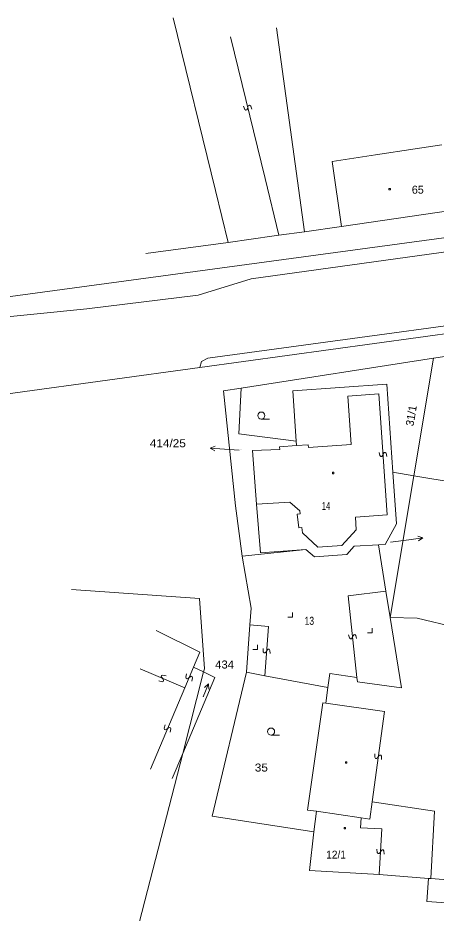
# Model space of a CAD drawing. Extents: x -736847 to -736508, y -1028413 to -1028271.
# Drawn here: x -736724.5 to -736680.1, y -1028365.6 to -1028270.6 of the extents above; entities that cross this region are included whole.
import ezdxf
from ezdxf.enums import TextEntityAlignment as Align

# ---------------------------------------------------------------- set-up
doc = ezdxf.new("R2010")
doc.units = 0
doc.header["$LTSCALE"] = 0.2
doc.layers.add('1', color=7, linetype='Continuous', lineweight=13)
doc.layers.add('2', color=7, linetype='Continuous', lineweight=13)

msp = doc.modelspace()

# ---------------------------------------------------------------- linework, layer by layer
at = {"layer": '1'}
for p, q in [((-736708.02, -1028270.56), (-736703.53, -1028288.89)), ((-736697.06, -1028271.61), (-736694.09, -1028293.26)), ((-736701.96, -1028272.58), (-736698.28, -1028287.61)), ((-736682.37, -1028284.46), (-736686.58, -1028285.1)), ((-736679.54, -1028284.04), (-736682.37, -1028284.46)), ((-736686.58, -1028285.1), (-736691.15, -1028285.79)), ((-736690.18, -1028292.72), (-736691.15, -1028285.79)), ((-736698.28, -1028287.61), (-736696.81, -1028293.63)), ((-736748.87, -1028303.31), (-736632.81, -1028287.63)), ((-736702.18, -1028294.39), (-736703.53, -1028288.89)), ((-736696.81, -1028293.63), (-736694.09, -1028293.26)), ((-736696.81, -1028293.63), (-736697.3, -1028293.7)), ((-736676.66, -1028306.12), (-736680.4, -1028306.7)), ((-736700.82, -1028309.86), (-736680.4, -1028306.7)), ((-736680.4, -1028306.7), (-736682.5, -1028319.17)), ((-736685.37, -1028309.44), (-736695.35, -1028310.15)), ((-736684.72, -1028318.78), (-736685.37, -1028309.44)), ((-736702.69, -1028310.15), (-736700.82, -1028309.86)), ((-736700.82, -1028309.86), (-736701.05, -1028314.73)), ((-736695.35, -1028310.15), (-736694.97, -1028315.51)), ((-736689.49, -1028310.7), (-736686.2, -1028310.48)), ((-736689.49, -1028310.7), (-736689.15, -1028315.84)), ((-736686.2, -1028310.48), (-736685.34, -1028323.33)), ((-736701.05, -1028314.73), (-736694.97, -1028315.51)), ((-736694.94, -1028315.97), (-736696.74, -1028316.09)), ((-736696.73, -1028316.37), (-736696.74, -1028316.09)), ((-736694.97, -1028315.51), (-736694.94, -1028315.97)), ((-736694.94, -1028315.97), (-736693.7, -1028315.87)), ((-736693.7, -1028315.87), (-736693.68, -1028316.17)), ((-736693.68, -1028316.17), (-736689.15, -1028315.84)), ((-736701.03, -1028316.44), (-736702.6, -1028316.34)), ((-736699.6, -1028316.49), (-736696.73, -1028316.37)), ((-736699.18, -1028322.18), (-736699.6, -1028316.49)), ((-736684.72, -1028318.78), (-736684.33, -1028324.26)), ((-736684.72, -1028318.78), (-736682.5, -1028319.17)), ((-736695.66, -1028321.96), (-736699.18, -1028322.18)), ((-736698.75, -1028327.35), (-736699.18, -1028322.18)), ((-736694.6, -1028322.9), (-736695.66, -1028321.96)), ((-736694.55, -1028323.21), (-736694.86, -1028323.26)), ((-736694.86, -1028323.26), (-736694.7, -1028324.7)), ((-736694.6, -1028322.9), (-736694.55, -1028323.21)), ((-736685.34, -1028323.33), (-736688.7, -1028323.55)), ((-736688.7, -1028323.55), (-736688.62, -1028324.9)), ((-736694.7, -1028324.7), (-736694.38, -1028324.66)), ((-736694.38, -1028324.66), (-736694.32, -1028325.23)), ((-736685.53, -1028326.45), (-736684.33, -1028324.26)), ((-736692.7, -1028326.74), (-736694.32, -1028325.23)), ((-736688.62, -1028324.9), (-736690.12, -1028326.57)), ((-736690.12, -1028326.57), (-736692.7, -1028326.74)), ((-736686.26, -1028326.5), (-736688.82, -1028326.65)), ((-736686.26, -1028326.5), (-736685.53, -1028326.45)), ((-736684.99, -1028326.23), (-736683.04, -1028325.97)), ((-736700.72, -1028327.72), (-736693.94, -1028326.99)), ((-736693.94, -1028326.99), (-736698.75, -1028327.35)), ((-736693.02, -1028327.76), (-736693.94, -1028326.99)), ((-736689.62, -1028327.51), (-736693.02, -1028327.76)), ((-736688.82, -1028326.65), (-736689.62, -1028327.51)), ((-736699.76, -1028333.24), (-736700.72, -1028327.72)), ((-736699.89, -1028335.01), (-736697.92, -1028335.16)), ((-736685.01, -1028334.2), (-736682.13, -1028334.28)), ((-736685.01, -1028334.2), (-736683.82, -1028341.69)), ((-736661.35, -1028339.36), (-736682.13, -1028334.28)), ((-736709.82, -1028335.6), (-736705.19, -1028337.88)), ((-736698.31, -1028340.39), (-736697.92, -1028335.16)), ((-736705.86, -1028339.48), (-736705.19, -1028337.88)), ((-736706.8, -1028341.69), (-736711.54, -1028339.68)), ((-736705.86, -1028339.48), (-736704.8, -1028340)), ((-736704.72, -1028339.68), (-736704.8, -1028340)), ((-736704.8, -1028340), (-736707.02, -1028348.65)), ((-736703.61, -1028340.59), (-736707.02, -1028348.65)), ((-736704.8, -1028340), (-736703.61, -1028340.59)), ((-736703.9, -1028355.29), (-736700.26, -1028340.03)), ((-736683.82, -1028341.69), (-736688.48, -1028341.04)), ((-736707.02, -1028348.65), (-736711.92, -1028367.73)), ((-736707.02, -1028348.65), (-736708.14, -1028351.3)), ((-736692.83, -1028354.78), (-736693.77, -1028354.66)), ((-736680.68, -1028361.93), (-736680.3, -1028354.79)), ((-736693.09, -1028356.97), (-736703.9, -1028355.29)), ((-736688.07, -1028355.5), (-736687.18, -1028355.63)), ((-736693.57, -1028361.09), (-736686.16, -1028361.49)), ((-736686.16, -1028361.49), (-736680.95, -1028361.91)), ((-736671.76, -1028362.66), (-736680.68, -1028361.93))]:
    msp.add_line(p, q, dxfattribs=at)
for points in [[(-736847.11, -1028304.1), (-736847.14, -1028305.98), (-736789.15, -1028305.56), (-736765.17, -1028304.89), (-736752.25, -1028304.39), (-736741.06, -1028303.76), (-736733.02, -1028303.04), (-736717.19, -1028301.44), (-736705.39, -1028300.01), (-736699.76, -1028298.26), (-736645.39, -1028290.74), (-736606.84, -1028284.63), (-736586.11, -1028282.62), (-736567.68, -1028281.15), (-736549.73, -1028280.36), (-736529.75, -1028279.79), (-736523.28, -1028279.48), (-736516.84, -1028278.77), (-736513.8, -1028278.17), (-736508.09, -1028276.55)], [(-736694.09, -1028293.26), (-736690.18, -1028292.72), (-736675.43, -1028290.55), (-736672.4, -1028290.07), (-736659.12, -1028288.32), (-736657.95, -1028288.15), (-736651.64, -1028287.22), (-736648.15, -1028286.77), (-736642.63, -1028286), (-736641.29, -1028285.81)], [(-736697.3, -1028293.7), (-736702.18, -1028294.39), (-736710.94, -1028295.58)], [(-736617.32, -1028295.6), (-736658.87, -1028301.31), (-736705.21, -1028307.67), (-736744.41, -1028313.05)], [(-736705.21, -1028307.67), (-736705.02, -1028307.05), (-736704.37, -1028306.69), (-736661.17, -1028300.8), (-736659.94, -1028300.93), (-736658.87, -1028301.31)], [(-736702.69, -1028310.15), (-736701.41, -1028322.36), (-736700.72, -1028327.72)], [(-736685.01, -1028334.2), (-736682.5, -1028319.17), (-736678.02, -1028319.93), (-736677.09, -1028310.49)], [(-736686.26, -1028326.5), (-736685.46, -1028331.41), (-736685.01, -1028334.2)], [(-736718.81, -1028331.23), (-736705.22, -1028332.2), (-736704.72, -1028339.68)], [(-736688.53, -1028340.59), (-736689.45, -1028331.92), (-736685.46, -1028331.41)], [(-736700.26, -1028340.03), (-736699.89, -1028335.01), (-736699.76, -1028333.24)], [(-736710.45, -1028350.32), (-736706.8, -1028341.69), (-736705.86, -1028339.48)], [(-736660.48, -1028339.57), (-736666.59, -1028365.34), (-736681.13, -1028364.37)], [(-736691.61, -1028341.63), (-736698.31, -1028340.39), (-736700.26, -1028340.03)], [(-736691.85, -1028343.31), (-736691.61, -1028341.63), (-736691.41, -1028340.16)], [(-736691.41, -1028340.16), (-736688.53, -1028340.59), (-736688.48, -1028341.04)], [(-736693.77, -1028354.66), (-736692.15, -1028343.27), (-736691.85, -1028343.31)], [(-736686.93, -1028353.8), (-736685.62, -1028344.21), (-736691.85, -1028343.31)], [(-736680.3, -1028354.79), (-736686.93, -1028353.8), (-736687.18, -1028355.63)], [(-736688.07, -1028355.5), (-736692.83, -1028354.78), (-736693.09, -1028356.97), (-736693.57, -1028361.09)], [(-736688.07, -1028355.5), (-736688.17, -1028356.53), (-736685.9, -1028356.65), (-736686.16, -1028361.49)], [(-736681.13, -1028364.37), (-736680.95, -1028361.91), (-736680.68, -1028361.93)]]:
    msp.add_lwpolyline(points, dxfattribs=at)
at = {"layer": '2'}
for p, q in [((-736698.68, -1028313.15), (-736697.805, -1028313.15)), ((-736704.096, -1028316.241), (-736703.581, -1028316.024)), ((-736681.552, -1028325.773), (-736682.015, -1028326.086)), ((-736695.36, -1028334.17), (-736695.86, -1028334.17)), ((-736695.36, -1028334.17), (-736695.36, -1028333.67)), ((-736686.93, -1028335.86), (-736687.43, -1028335.86)), ((-736686.93, -1028335.86), (-736686.93, -1028335.36)), ((-736699.07, -1028337.61), (-736699.57, -1028337.61)), ((-736699.07, -1028337.61), (-736699.07, -1028337.11)), ((-736704.288, -1028341.263), (-736704.247, -1028341.82)), ((-736697.64, -1028346.7), (-736696.765, -1028346.7))]:
    msp.add_line(p, q, dxfattribs=at)
for points in [[(-736699.672, -1028280.242), (-736699.803, -1028279.914), (-736699.924, -1028279.841), (-736700.021, -1028279.865), (-736700.095, -1028279.985), (-736700.144, -1028280.204), (-736700.218, -1028280.324), (-736700.315, -1028280.348), (-736700.436, -1028280.275), (-736700.567, -1028279.947)], [(-736702.6, -1028316.34), (-736704.096, -1028316.241), (-736703.614, -1028316.523)], [(-736685.354, -1028317.127), (-736685.427, -1028316.781), (-736685.533, -1028316.688), (-736685.633, -1028316.695), (-736685.726, -1028316.801), (-736685.813, -1028317.008), (-736685.906, -1028317.114), (-736686.006, -1028317.121), (-736686.112, -1028317.028), (-736686.185, -1028316.682)], [(-736683.04, -1028325.97), (-736681.552, -1028325.773), (-736682.081, -1028325.591)], [(-736688.565, -1028336.461), (-736688.652, -1028336.118), (-736688.762, -1028336.029), (-736688.861, -1028336.04), (-736688.95, -1028336.15), (-736689.029, -1028336.359), (-736689.118, -1028336.469), (-736689.217, -1028336.48), (-736689.327, -1028336.391), (-736689.414, -1028336.048)], [(-736698.495, -1028337.495), (-736698.471, -1028337.848), (-736698.379, -1028337.955), (-736698.279, -1028337.963), (-736698.172, -1028337.871), (-736698.057, -1028337.679), (-736697.95, -1028337.586), (-736697.85, -1028337.594), (-736697.758, -1028337.701), (-736697.734, -1028338.054)], [(-736708.783, -1028340.414), (-736709.125, -1028340.323), (-736709.256, -1028340.376), (-736709.295, -1028340.468), (-736709.242, -1028340.599), (-736709.097, -1028340.77), (-736709.044, -1028340.901), (-736709.083, -1028340.993), (-736709.214, -1028341.046), (-736709.556, -1028340.955)], [(-736706.6, -1028340.198), (-736706.691, -1028340.54), (-736706.638, -1028340.671), (-736706.546, -1028340.71), (-736706.415, -1028340.657), (-736706.244, -1028340.512), (-736706.113, -1028340.459), (-736706.021, -1028340.498), (-736705.968, -1028340.629), (-736706.059, -1028340.971)], [(-736704.86, -1028342.65), (-736704.288, -1028341.263), (-736704.71, -1028341.63)], [(-736708.896, -1028345.618), (-736708.986, -1028345.96), (-736708.933, -1028346.091), (-736708.841, -1028346.13), (-736708.71, -1028346.077), (-736708.54, -1028345.932), (-736708.408, -1028345.879), (-736708.316, -1028345.918), (-736708.263, -1028346.049), (-736708.353, -1028346.391)], [(-736686.637, -1028348.703), (-736686.635, -1028349.056), (-736686.549, -1028349.169), (-736686.45, -1028349.182), (-736686.338, -1028349.097), (-736686.211, -1028348.912), (-736686.099, -1028348.827), (-736686, -1028348.84), (-736685.914, -1028348.953), (-736685.912, -1028349.306)], [(-736686.416, -1028358.798), (-736686.384, -1028359.151), (-736686.29, -1028359.256), (-736686.19, -1028359.261), (-736686.085, -1028359.167), (-736685.974, -1028358.972), (-736685.869, -1028358.878), (-736685.769, -1028358.883), (-736685.675, -1028358.988), (-736685.643, -1028359.341)]]:
    msp.add_lwpolyline(points, dxfattribs=at)
for points in [[(-736685.14, -1028288.67), (-736684.99, -1028288.67), (-736684.99, -1028288.82), (-736685.14, -1028288.82)], [(-736691.13, -1028318.8), (-736690.98, -1028318.8), (-736690.98, -1028318.95), (-736691.13, -1028318.95)], [(-736689.76, -1028349.52), (-736689.61, -1028349.52), (-736689.61, -1028349.67), (-736689.76, -1028349.67)], [(-736689.9, -1028356.5), (-736689.75, -1028356.5), (-736689.75, -1028356.65), (-736689.9, -1028356.65)]]:
    msp.add_lwpolyline(points, close=True, dxfattribs=at)
for centre in [(-736698.68, -1028312.775), (-736697.64, -1028346.325)]:
    msp.add_circle(centre, 0.375, dxfattribs=at)

# ---------------------------------------------------------------- texts
msp.add_text('65', height=0.85, dxfattribs=at).set_placement((-736682.71, -1028289.22))
msp.add_text('31/1', height=0.85, rotation=80.441, dxfattribs=at).set_placement((-736682.54, -1028313.95))
at = {"layer": '2', "width": 1.1}
msp.add_text('414/25', height=0.85, dxfattribs=at).set_placement((-736706.686, -1028316.14), align=Align.RIGHT)
at = {"layer": '2'}
for s, height, width, p in [('414/25', 0.05, 1.1, (-736701.03, -1028316.44)), ('14', 0.85, 0.7, (-736692.25, -1028322.8)), ('420', 0.05, 1.1, (-736684.99, -1028326.23)), ('13', 0.85, 0.8, (-736694.09, -1028334.99)), ('434', 0.05, 1.05, (-736704.86, -1028342.65)), ('35', 0.85, 1.1, (-736699.37, -1028350.57)), ('12/1', 0.85, 0.95, (-736691.8, -1028359.82))]:
    msp.add_text(s, height=height, dxfattribs=dict(at, width=width)).set_placement(p)
at = {"layer": '2', "width": 1.05}
msp.add_text('434', height=0.85, dxfattribs=at).set_placement((-736702.574, -1028339.63), align=Align.CENTER)

doc.saveas('drawing.dxf')
